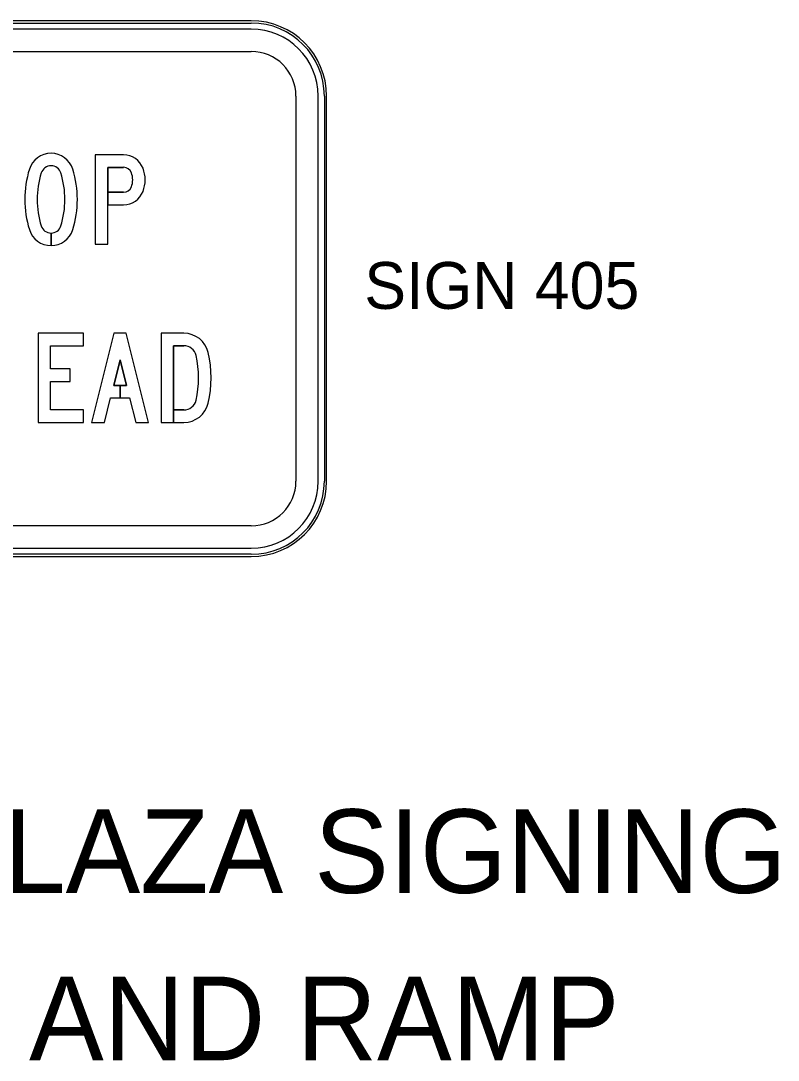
# Model space of a CAD drawing. Extents: x -63400 to -62632, y -1624834 to -1624417.
# Drawn here: x -62882.3 to -62837, y -1624821.5 to -1624759.4 of the extents above; entities that cross this region are included whole.
import ezdxf

# ---------------------------------------------------------------- set-up
doc = ezdxf.new("R2010")
doc.units = 0
for name, color, linetype in [('GSBWFill', 7, 'Continuous'), ('GSColorFill', 7, 'Continuous'), ('GSOutline', 7, 'Continuous'), ('TextLabel', 7, 'Continuous'), ('TextMisc', 7, 'Continuous')]:
    doc.layers.add(name, color=color, linetype=linetype)

msp = doc.modelspace()

# ---------------------------------------------------------------- linework, layer by layer
at = {"layer": 'GSBWFill'}
for p, q in [((-62880.469, -1624772.053), (-62880.469, -1624772.8)), ((-62880.469, -1624772.8), (-62880.469, -1624772.053)), ((-62872.532, -1624782.626), (-62873.143, -1624782.626))]:
    msp.add_line(p, q, dxfattribs=at)
for points in [[(-62876.14, -1624767.373), (-62877.829, -1624767.373), (-62877.829, -1624772.706), (-62877.082, -1624772.706), (-62877.082, -1624768.12), (-62876.14, -1624768.12)], [(-62876.14, -1624769.613), (-62877.082, -1624769.613), (-62877.082, -1624770.36), (-62876.14, -1624770.36)], [(-62872.532, -1624778.04), (-62873.89, -1624778.04), (-62873.89, -1624783.373), (-62873.143, -1624783.373), (-62873.143, -1624778.786), (-62872.532, -1624778.786)], [(-62873.143, -1624782.626), (-62873.143, -1624783.373), (-62872.532, -1624783.373)]]:
    msp.add_lwpolyline(points, dxfattribs=at)
for points in [[(-62880.503, -1624782.626), (-62880.503, -1624780.92), (-62879.335, -1624780.92), (-62879.335, -1624780.173), (-62880.503, -1624780.173), (-62880.503, -1624778.786), (-62878.53, -1624778.786), (-62878.53, -1624778.04), (-62881.25, -1624778.04), (-62881.25, -1624783.373), (-62878.53, -1624783.373), (-62878.53, -1624782.626)], [(-62876.343, -1624781.16), (-62876.727, -1624781.16), (-62876.343, -1624779.625), (-62875.96, -1624781.16), (-62876.343, -1624781.16), (-62876.343, -1624781.906), (-62875.773, -1624781.906), (-62875.406, -1624783.373), (-62874.637, -1624783.373), (-62875.97, -1624778.04), (-62876.717, -1624778.04), (-62878.05, -1624783.373), (-62877.281, -1624783.373), (-62876.914, -1624781.906), (-62876.343, -1624781.906)]]:
    msp.add_lwpolyline(points, close=True, dxfattribs=at)
for centre, radius, start, end in [((-62876.14, -1624768.626), 1.253, 21.1002, 90), ((-62876.14, -1624768.626), 0.507, 21.1002, 90), ((-62876.762, -1624768.866), 1.173, 338.89981, 21.1002), ((-62876.762, -1624768.866), 1.92, 338.8998, 21.10019), ((-62876.14, -1624769.106), 0.507, 270, 338.8998), ((-62876.14, -1624769.106), 1.253, 270, 338.8998)]:
    msp.add_arc(centre, radius, start, end, dxfattribs=at)
for centre, major_axis, ratio, start_param, end_param in [((-62880.469, -1624768.64), (0, 1.36), 0.999994, 5.014824, 7.551546), ((-62880.469, -1624768.64), (0, 0.613), 0.999994, 5.014824, 7.551546), ((-62875.982, -1624770.04), (0, 6.06), 0.999994, 1.268361, 1.873232), ((-62875.982, -1624770.04), (0, 5.314), 0.999994, 1.268361, 1.873232), ((-62884.956, -1624770.04), (0, 5.314), 0.999994, 4.409954, 5.014824), ((-62884.956, -1624770.04), (0, 6.06), 0.999994, 4.409954, 5.014824), ((-62880.469, -1624771.44), (0, 0.613), 0.999994, 1.873232, 3.141593), ((-62880.469, -1624771.44), (0, 0.613), 0.999994, 3.142027, 4.409954), ((-62880.469, -1624771.44), (0, 1.36), 0.999994, 1.873232, 3.141593), ((-62880.469, -1624771.44), (0, 1.36), 0.999994, 3.141789, 4.409954), ((-62872.532, -1624779.533), (0, 1.493), 0.999992, 4.941184, 6.283185), ((-62872.532, -1624779.533), (0, 0.747), 0.999992, 4.941184, 6.283185), ((-62877.57, -1624780.706), (0, 6.667), 0.999992, 4.483594, 4.941184), ((-62877.57, -1624780.706), (0, 5.92), 0.999992, 4.483594, 4.941184), ((-62872.532, -1624781.88), (0, 0.747), 0.999992, 3.141593, 4.483594), ((-62872.532, -1624781.88), (0, 1.493), 0.999992, 3.141593, 4.483594)]:
    msp.add_ellipse(centre, major_axis=major_axis, ratio=ratio, start_param=start_param, end_param=end_param, dxfattribs=at)
at = {"layer": 'GSColorFill'}
for p, q in [((-62868.5, -1624759.357), (-62923.531, -1624759.357)), ((-62868.5, -1624759.357), (-62923.531, -1624759.357)), ((-62923.531, -1624759.49), (-62868.5, -1624759.49)), ((-62868.5, -1624759.857), (-62923.531, -1624759.857)), ((-62923.531, -1624761.19), (-62868.5, -1624761.19)), ((-62865.833, -1624763.857), (-62865.833, -1624786.889)), ((-62864.5, -1624786.889), (-62864.5, -1624763.857)), ((-62864.133, -1624763.857), (-62864.133, -1624786.889)), ((-62864, -1624786.889), (-62864, -1624763.857)), ((-62864, -1624786.889), (-62864, -1624763.857)), ((-62880.469, -1624772.053), (-62880.469, -1624772.8)), ((-62880.469, -1624772.8), (-62880.469, -1624772.053)), ((-62872.532, -1624782.626), (-62873.143, -1624782.626)), ((-62868.5, -1624789.556), (-62923.518, -1624789.556)), ((-62923.518, -1624790.889), (-62868.5, -1624790.889)), ((-62923.531, -1624791.389), (-62868.5, -1624791.389)), ((-62868.5, -1624791.256), (-62923.53, -1624791.256)), ((-62923.53, -1624791.389), (-62868.5, -1624791.389))]:
    msp.add_line(p, q, dxfattribs=at)
for points in [[(-62876.14, -1624767.373), (-62877.829, -1624767.373), (-62877.829, -1624772.706), (-62877.082, -1624772.706), (-62877.082, -1624768.12), (-62876.14, -1624768.12)], [(-62876.14, -1624769.613), (-62877.082, -1624769.613), (-62877.082, -1624770.36), (-62876.14, -1624770.36)], [(-62872.532, -1624778.04), (-62873.89, -1624778.04), (-62873.89, -1624783.373), (-62873.143, -1624783.373), (-62873.143, -1624778.786), (-62872.532, -1624778.786)], [(-62873.143, -1624782.626), (-62873.143, -1624783.373), (-62872.532, -1624783.373)]]:
    msp.add_lwpolyline(points, dxfattribs=at)
for points in [[(-62880.503, -1624782.626), (-62880.503, -1624780.92), (-62879.335, -1624780.92), (-62879.335, -1624780.173), (-62880.503, -1624780.173), (-62880.503, -1624778.786), (-62878.53, -1624778.786), (-62878.53, -1624778.04), (-62881.25, -1624778.04), (-62881.25, -1624783.373), (-62878.53, -1624783.373), (-62878.53, -1624782.626)], [(-62876.343, -1624781.16), (-62876.727, -1624781.16), (-62876.343, -1624779.625), (-62875.96, -1624781.16), (-62876.343, -1624781.16), (-62876.343, -1624781.906), (-62875.773, -1624781.906), (-62875.406, -1624783.373), (-62874.637, -1624783.373), (-62875.97, -1624778.04), (-62876.717, -1624778.04), (-62878.05, -1624783.373), (-62877.281, -1624783.373), (-62876.914, -1624781.906), (-62876.343, -1624781.906)]]:
    msp.add_lwpolyline(points, close=True, dxfattribs=at)
for centre, radius, start, end in [((-62868.5, -1624763.857), 4.5, 0, 90), ((-62868.5, -1624763.857), 4.5, 0, 90), ((-62868.5, -1624763.857), 4.367, 0, 90), ((-62868.5, -1624763.857), 4, 0, 90), ((-62868.5, -1624763.857), 2.667, 0, 90), ((-62876.14, -1624768.626), 1.253, 21.1002, 90), ((-62876.14, -1624768.626), 0.507, 21.1002, 90), ((-62876.762, -1624768.866), 1.173, 338.89981, 21.1002), ((-62876.762, -1624768.866), 1.92, 338.8998, 21.10019), ((-62876.14, -1624769.106), 0.507, 270, 338.8998), ((-62876.14, -1624769.106), 1.253, 270, 338.8998), ((-62868.5, -1624786.889), 4, 270, 0), ((-62868.5, -1624786.889), 2.667, 270, 0), ((-62868.5, -1624786.889), 4.5, 270, 0), ((-62868.5, -1624786.889), 4.367, 270, 0), ((-62868.5, -1624786.889), 4.5, 270, 0)]:
    msp.add_arc(centre, radius, start, end, dxfattribs=at)
for centre, major_axis, ratio, start_param, end_param in [((-62880.469, -1624768.64), (0, 1.36), 0.999994, 5.014824, 7.551546), ((-62880.469, -1624768.64), (0, 0.613), 0.999994, 5.014824, 7.551546), ((-62875.982, -1624770.04), (0, 6.06), 0.999994, 1.268361, 1.873232), ((-62875.982, -1624770.04), (0, 5.314), 0.999994, 1.268361, 1.873232), ((-62884.956, -1624770.04), (0, 5.314), 0.999994, 4.409954, 5.014824), ((-62884.956, -1624770.04), (0, 6.06), 0.999994, 4.409954, 5.014824), ((-62880.469, -1624771.44), (0, 0.613), 0.999994, 1.873232, 3.141593), ((-62880.469, -1624771.44), (0, 0.613), 0.999994, 3.142027, 4.409954), ((-62880.469, -1624771.44), (0, 1.36), 0.999994, 1.873232, 3.141593), ((-62880.469, -1624771.44), (0, 1.36), 0.999994, 3.141789, 4.409954), ((-62872.532, -1624779.533), (0, 1.493), 0.999992, 4.941184, 6.283185), ((-62872.532, -1624779.533), (0, 0.747), 0.999992, 4.941184, 6.283185), ((-62877.57, -1624780.706), (0, 6.667), 0.999992, 4.483594, 4.941184), ((-62877.57, -1624780.706), (0, 5.92), 0.999992, 4.483594, 4.941184), ((-62872.532, -1624781.88), (0, 0.747), 0.999992, 3.141593, 4.483594), ((-62872.532, -1624781.88), (0, 1.493), 0.999992, 3.141593, 4.483594)]:
    msp.add_ellipse(centre, major_axis=major_axis, ratio=ratio, start_param=start_param, end_param=end_param, dxfattribs=at)
at = {"layer": 'GSOutline'}
for p, q in [((-62876.14, -1624767.373), (-62877.829, -1624767.373)), ((-62873.143, -1624782.626), (-62872.532, -1624782.626)), ((-62872.532, -1624783.373), (-62872.532, -1624783.373))]:
    msp.add_line(p, q, dxfattribs=at)
for points in [[(-62877.829, -1624767.373), (-62877.829, -1624772.706), (-62877.082, -1624772.706), (-62877.082, -1624770.36), (-62876.14, -1624770.36)], [(-62876.14, -1624768.12), (-62877.082, -1624768.12), (-62877.082, -1624769.613), (-62876.14, -1624769.613)], [(-62872.532, -1624778.04), (-62873.89, -1624778.04), (-62873.89, -1624783.373), (-62872.532, -1624783.373)], [(-62872.532, -1624778.786), (-62873.143, -1624778.786), (-62873.143, -1624782.626)]]:
    msp.add_lwpolyline(points, dxfattribs=at)
for points in [[(-62880.503, -1624782.626), (-62880.503, -1624780.92), (-62879.335, -1624780.92), (-62879.335, -1624780.173), (-62880.503, -1624780.173), (-62880.503, -1624778.786), (-62878.53, -1624778.786), (-62878.53, -1624778.04), (-62881.25, -1624778.04), (-62881.25, -1624783.373), (-62878.53, -1624783.373), (-62878.53, -1624782.626)], [(-62876.914, -1624781.906), (-62875.773, -1624781.906), (-62875.406, -1624783.373), (-62874.637, -1624783.373), (-62875.97, -1624778.04), (-62876.717, -1624778.04), (-62878.05, -1624783.373), (-62877.281, -1624783.373)], [(-62875.96, -1624781.16), (-62876.343, -1624779.625), (-62876.727, -1624781.16)]]:
    msp.add_lwpolyline(points, close=True, dxfattribs=at)
for centre, radius, start, end in [((-62876.14, -1624768.626), 1.253, 21.1002, 90), ((-62876.14, -1624768.626), 0.507, 21.1002, 90), ((-62876.762, -1624768.866), 1.173, 338.8998, 21.10019), ((-62876.762, -1624768.866), 1.92, 338.8998, 21.10019), ((-62876.14, -1624769.106), 0.507, 270, 338.8998), ((-62876.14, -1624769.106), 1.253, 270, 338.8998)]:
    msp.add_arc(centre, radius, start, end, dxfattribs=at)
for centre, major_axis, ratio, start_param, end_param in [((-62880.469, -1624768.64), (0, 1.36), 0.999994, 5.014824, 7.551546), ((-62880.469, -1624768.64), (0, 0.613), 0.999994, 5.014824, 7.551546), ((-62875.982, -1624770.04), (0, 6.06), 0.999994, 1.268361, 1.873232), ((-62875.982, -1624770.04), (0, 5.314), 0.999994, 1.268361, 1.873232), ((-62884.956, -1624770.04), (0, 5.314), 0.999994, 4.409954, 5.014824), ((-62884.956, -1624770.04), (0, 6.06), 0.999994, 4.409954, 5.014824), ((-62880.469, -1624771.44), (0, 0.613), 0.999994, 1.873232, 4.409954), ((-62880.469, -1624771.44), (0, 1.36), 0.999994, 1.873232, 4.409954), ((-62872.532, -1624779.533), (0, 1.493), 0.999992, 4.941184, 6.283185), ((-62872.532, -1624779.533), (0, 0.747), 0.999992, 4.941184, 6.283185), ((-62877.57, -1624780.706), (0, 6.667), 0.999992, 4.483594, 4.941184), ((-62877.57, -1624780.706), (0, 5.92), 0.999992, 4.483594, 4.941184), ((-62872.532, -1624781.88), (0, 0.747), 0.999992, 3.141593, 4.483594), ((-62872.532, -1624781.88), (0, 1.493), 0.999992, 3.141593, 4.483594)]:
    msp.add_ellipse(centre, major_axis=major_axis, ratio=ratio, start_param=start_param, end_param=end_param, dxfattribs=at)

# ---------------------------------------------------------------- texts
at = {"layer": 'TextLabel'}
msp.add_text('SIGN 405', height=2.8, dxfattribs=at).set_placement((-62861.746, -1624776.582))
at = {"layer": 'TextMisc'}
for s, p in [(' INTERIOR PLAZA SIGNING ', (-62923.437, -1624811.508)), ('   MAINLINE AND RAMP    ', (-62920.792, -1624821.508))]:
    msp.add_text(s, height=5, rotation=360, dxfattribs=at).set_placement(p)

doc.saveas('drawing.dxf')
